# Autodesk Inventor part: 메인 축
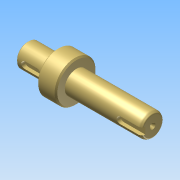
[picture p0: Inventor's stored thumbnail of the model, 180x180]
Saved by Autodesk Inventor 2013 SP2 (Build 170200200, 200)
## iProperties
Created: 2026-07
Part Number: 메인 축
Material: Generic
Document SubType Name: Modeling
Designer: 601
Density: 1 g/cm^3
Author: 601
변환 표준: STEP AP214IS
전처리기: Build: 200, Release: 2013 SP2 Update 6 - Date: Thu 07/17/2014
전송 단위: 밀리미터
불확실성: 0.01
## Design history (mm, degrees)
node "메인 축1"
node "솔리드1"
node "기준1"
